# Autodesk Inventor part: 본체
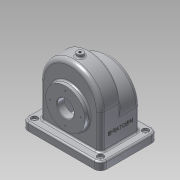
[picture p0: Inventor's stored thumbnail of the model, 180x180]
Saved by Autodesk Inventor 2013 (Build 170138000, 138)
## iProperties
Created: 2017-11
Part Number: 본체
Material: 알루미늄 6061
Document SubType Name: Modeling
Designer: Administrator
Mass: 1079.49 g
Surface Area: 1182.07 cm^2
Volume: 398.335 cm^3
Density: 2.71 g/cm^3
Author: Administrator
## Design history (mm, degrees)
sketch "스케치4"
  geometry: L1 (-58, -19)-(58, -19); L2 (58, -19)-(58, 19); L3 (58, 19)-(-58, 19); L4 (-58, 19)-(-58, -19); L5 (-58, -19)-(58, 19); L6 (58, -19)-(-58, 19); 1 further point
  constraints: 12 end point, 2 midpoint, 2 parallel, 1 horizontal, 1 perpendicular
  dimensions: "d8" = 116 distance of L2.end L3.end; "d11" = 38 distance of L3.end L1.start
extrude "돌출2" new body sketch "스케치4" distance "d12" = 138; taper "d13" = 0 deg
sketch "스케치5"
  geometry: L1 (116, 0)-(0, 0) reference; L2 (0, 0)-(0, -138) reference; L3 (116, 0)-(116, -138) reference; A1 r 58 centre (58, -57) between (68.724, 0) and (47.276, 0); A2 r 58 centre (58, -57) between (0, -57) and (116, -57); 2 further points
  constraints: 4 point on circle, 4 point on line, 2 centre point, 1 midpoint, 1 vertical alignment
  dimensions: "d14" = 57 distance from line of L1 A1.centre; "d16" = 58 radius of A2
extrude "돌출3" join sketch "스케치5" distance "d17" = 38; taper "d18" = 0 deg
fillet "모깎기2" dims "d19" = 58
feature "쉘1" dims "d20" = 5
sketch "스케치6"
  geometry: L1 (0, 0)-(116, 0) reference; C1 r 37.5 at (58, 65); A1 r 58 centre (58, 80) between (116, 80) and (0, 80) reference; 1 further point
  constraints: 1 centre point, 1 vertical alignment
  dimensions: "d29" = 65 distance from line of L1 C1.centre; "d30" = 75 diameter of C1
extrude "돌출4" join sketch "스케치6" distance "d23" = 9; taper "d24" = 0 deg
sketch "스케치9"
  geometry: C1 r 37.5 at (0, 0) reference; C2 r 16 at (0, 0); 1 further point
  constraints: 1 centre point, 1 coincident
  dimensions: "d31" = 32 diameter of C2
extrude "돌출6" cut sketch "스케치9" distance "d33" = 15; taper "d34" = 0 deg
sketch "스케치10"
  geometry: L1 (116, 0)-(0, 0) reference; C1 r 31 at (58, -65); 2 further points
  constraints: 1 centre point, 1 midpoint, 1 vertical alignment
  dimensions: "d35" = 65 distance from line of L1 C1.centre; "d36" = 62 diameter of C1
extrude "돌출7" join sketch "스케치10" distance "d37" = 10; taper "d38" = 0 deg
sketch "스케치11"
  geometry: C1 r 31 at (0, 0) reference; C2 r 16 at (0, 0); 1 further point
  constraints: 1 centre point, 1 coincident
  dimensions: "d39" = 32 diameter of C2
extrude "돌출8" cut sketch "스케치11" distance "d41" = 15; taper "d42" = 0 deg
sketch "스케치12"
  geometry: L1 (-53, -14)-(-53, 52) reference; L2 (58, -19)-(-58, -19) reference; L3 (58, -19)-(58, 57) reference; L4 (-58, 57)-(58, 57) reference; L5 (-58, -19)-(-58, 57) reference; L6 (75, 74)-(-75, 74); L7 (-75, 74)-(-75, -36); L8 (-75, -36)-(75, -36); L9 (75, -36)-(75, 74); L10 (75, 74)-(-75, -36); L11 (-75, 74)-(75, -36); 5 further points
  constraints: 12 end point, 5 midpoint, 2 parallel, 1 horizontal, 1 horizontal alignment, 1 perpendicular, 1 vertical alignment
  dimensions: "d43" = 150 distance of L7.end L8.end; "d45" = 110 distance of L8.end L6.start
extrude "돌출9" join sketch "스케치12" distance "d46" = 15; taper "d47" = 0 deg
fillet "모깎기3" dims "d48" = 8
fillet "모깎기4" dims "d49" = 3
fillet "모깎기5" dims "d50" = 12
sketch "스케치13"
  geometry: C1 r 6 at (-63, 62); C2 r 6 at (-63, -24); C3 r 6 at (63, 62); C4 r 6 at (63, -24); A1 r 12 centre (-63, 62) between (-63, 74) and (-75, 62) reference; A2 r 12 centre (-63, -24) between (-75, -24) and (-63, -36) reference; A3 r 12 centre (63, -24) between (63, -36) and (75, -24) reference; A4 r 12 centre (63, 62) between (75, 62) and (63, 74) reference; 1 further point
  constraints: 4 centre point, 4 coincident, 3 equal radius
  dimensions: "d51" = 12 diameter of C1
extrude "돌출10" cut sketch "스케치13" distance "d53" = 5; taper "d54" = 0 deg
sketch "스케치14"
  geometry: C1 r 6 at (0, 0) reference; C2 r 6 at (0, 86) reference; C3 r 6 at (-126, 86) reference; C4 r 6 at (-126, 0) reference; C5 r 2.5 at (-126, 86); C6 r 2.5 at (0, 86); C7 r 2.5 at (0, 0); C8 r 2.5 at (-126, 0); 1 further point
  constraints: 4 centre point, 4 coincident, 3 equal radius
  dimensions: "d55" = 5 diameter of C5
extrude "돌출11" cut sketch "스케치14" stored distance "d57" = 5; taper "d58" = 0 deg
fillet "모깎기6" dims "d59" = 3
sketch "스케치15" dims "d60" = 58
  geometry: C1 r 16 at (0, 0) reference; C2 r 37.5 at (0, 0) reference; 3 further points
  constraints: 2 vertical alignment, 1 coincident, 2 other
hole "구멍1" sketch "스케치15" at (0, 29) diameter "d62" = 2.459; stored, may be unused: countersink angle "d66" = 90 deg, drill point angle "d68" = 118 deg; dims "d63" = 6, "d64" = 4, "d65" = 2, "d67" = 8
sketch "스케치16" dims "d72" = 52
  geometry: C1 r 16 at (0, 0) reference; C2 r 31 at (0, 0) reference; 3 further points
  constraints: 2 vertical alignment, 1 coincident, 2 other
hole "구멍2" sketch "스케치16" at (0, -26) diameter "d74" = 2.459; stored, may be unused: countersink angle "d78" = 90 deg, drill point angle "d80" = 118 deg; dims "d75" = 6, "d76" = 4, "d77" = 2, "d79" = 8
chamfer "모따기1" distance "d84" = 1; stored, may be unused: second distance "d85" = 2, angle "d86" = 45 deg
node "작업 평면1"
sketch "스케치18"
  geometry: L1 (50, -19)-(-50, -19) reference; C1 r 6 at (0, 0); 2 further points
  constraints: 1 centre point, 1 midpoint, 1 vertical alignment
  dimensions: "d88" = 19 distance from line of L1 C1.centre; "d89" = 12 diameter of C1
extrude "돌출12" join sketch "스케치18" stored distance "d90" = 5; taper "d91" = 0 deg
sketch "스케치19"
  geometry: C1 r 6 at (0, 0) reference; 1 further point
  constraints: 1 coincident
hole "구멍3" sketch "스케치19" at (0, 0) diameter "d92" = 4.459; stored, may be unused: countersink angle "d96" = 90 deg, drill point angle "d98" = 118 deg; dims "d93" = 6, "d94" = 4, "d95" = 2, "d97" = 8
fillet "모깎기7" dims "d99" = 3
node "작업 평면2"
sketch "스케치20"
  geometry: L1 (-25.602, 5.113)-(-25.602, 54.887); L2 (-25.602, 54.887)-(-18.398, 54.887); L3 (-18.398, 54.887)-(-18.398, 5.113); L4 (-18.398, 5.113)-(-25.602, 5.113); L5 (-22, 5.113)-(-22, 54.887); L6 (-25.602, 30)-(-18.398, 30); L7 (-62, -8)-(0, -8) reference; L8 (18, -13)-(18, -25) reference; 1 further point
  constraints: 4 end point, 4 midpoint, 2 other
  dimensions: "d102" = 38 distance from line of L7 L6.end; "d103" = 40 distance between parallel lines of L8 L5
extrude "돌출13" join sketch "스케치20" stored distance "d104" = 5; taper "d105" = 0 deg
node "솔리드2"
pattern_circular "원형 패턴1" dims angle "d70" = 360 deg
pattern_circular "원형 패턴2" dims angle "d82" = 360 deg
other parameters: "d15" = 116, "d87" = 144, "d100" = 0.5
